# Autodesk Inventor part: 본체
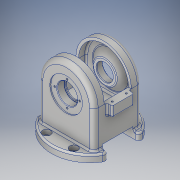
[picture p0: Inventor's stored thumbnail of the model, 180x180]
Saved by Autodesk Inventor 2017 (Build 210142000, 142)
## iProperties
Part Number: 본체
Material: 알루미늄 6061
Document SubType Name: Modeling
Designer: MRC
Density: 2.7 g/cm^3
Appearance: 알루미늄 - 평지
Mass: 1198.45 g
Surface Area: 1058.11 cm^2
Volume: 443.871 cm^3
Author: MRC
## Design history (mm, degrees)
sketch "스케치1"
  geometry: C1 r 71 at (0, 0); 1 further point
  constraints: 1 centre point, 1 coincident
  dimensions: "d0" = 142 diameter of C1
extrude "돌출1" new body sketch "스케치1" distance "d1" = 13; taper "d2" = 0 deg
sketch "스케치2"
  geometry: L1 (-71, 0)-(71, 0) reference; L2 (-51, 81)-(-51, 0); L3 (51, 81)-(51, 0); L4 (-51, 0)-(51, 0); A1 r 51 centre (0, 81) between (-51, 81) and (51, 81); 1 further point
  constraints: 6 end point, 2 point on circle, 2 point on line, 2 tangent, 1 centre point, 1 horizontal, 1 parallel, 1 perpendicular, 1 vertical alignment
  dimensions: "d3" = 102 diameter of A1; "d4" = 81 distance from line of A1.centre L1
extrude "돌출2" join sketch "스케치2" stored distance "d5" = 88; taper "d6" = 0 deg
node "작업 평면1"
sketch "스케치4"
  geometry: L1 (61, -20)-(-61, -20); L2 (-61, -20)-(-61, 20); L3 (-61, 20)-(61, 20); L4 (61, 20)-(61, -20); L5 (61, -20)-(-61, 20); L6 (-61, -20)-(61, 20); 1 further point
  constraints: 12 end point, 2 midpoint, 2 parallel, 1 horizontal, 1 perpendicular
  dimensions: "d10" = 40 distance of L3.end L1.start; "d11" = 122 distance of L1.start L1.end
extrude "돌출3" join sketch "스케치4" distance "d12" = 20; taper "d13" = 0 deg
sketch "스케치5"
  geometry: L1 (-89.487, -28)-(89.487, -28); L2 (89.487, -28)-(89.487, 28); L3 (89.487, 28)-(-89.487, 28); L4 (-89.487, 28)-(-89.487, -28); L5 (-89.487, -28)-(89.487, 28); L6 (89.487, -28)-(-89.487, 28); 1 further point
  constraints: 12 end point, 2 midpoint, 2 parallel, 1 horizontal, 1 perpendicular
  dimensions: "d14" = 56 distance of L1.end L2.end; "d15" = 178.97487 distance of L2.end L3.end
extrude "돌출4" cut sketch "스케치5" distance "d16" = 19; taper "d17" = 0 deg
sketch "스케치6"
  geometry: L1 (-51, 13)-(51, 13) reference; L2 (-51, 13)-(-51, 81) reference; L3 (51, 81)-(51, 13) reference; L4 (-46, 81)-(-46, 40); L5 (46, 40)-(46, 81); L6 (65.246, 0)-(-65.246, 0) reference; L7 (-46, 40)-(46, 40); A1 r 51 centre (0, 81) between (51, 81) and (-51, 81) reference; A2 r 46 centre (0, 81) between (46, 81) and (-46, 81); 1 further point
  constraints: 6 end point, 2 point on circle, 1 centre point, 1 horizontal
  dimensions: "d18" = 5 radial gap between concentric circles of A1 A2; "d20" = 5 distance between parallel lines of L3 L5; "d21" = 5 distance between parallel lines of L2 L4; "d22" = 40 distance between parallel lines of L6 L7
extrude "돌출5" cut sketch "스케치6" stored distance "d23" = 78; taper "d24" = 0 deg
sketch "스케치7"
  geometry: L1 (201.818, -25)-(81, -25); L2 (81, -25)-(81, 25); L3 (81, 25)-(201.818, 25); L4 (201.818, 25)-(201.818, -25); L5 (0, 71)-(0, 28) reference; 2 further points
  constraints: 8 end point, 2 parallel, 1 horizontal, 1 horizontal alignment, 1 midpoint, 1 perpendicular
  dimensions: "d25" = 50 distance of L3.end L1.start; "d26" = 81 distance between parallel lines of L2 L5; "d27" = 120.81817 distance of L2.end L3.end
extrude "돌출6" cut sketch "스케치7" stored distance "d28" = 78; taper "d29" = 0 deg
sketch "스케치8"
  geometry: L1 (81, -25)-(81, 25) reference; L2 (81, -44)-(81, -25) reference; L3 (13, 44)-(81, 44) reference; L4 (81, -44)-(13, -44) reference; L5 (81, -44)-(132, -44) reference; L6 (132, 44)-(81, 44) reference; L7 (81, 25)-(81, 39) reference; L8 (81, -44)-(81, 44); L9 (102.5, -27)-(81, -27); L10 (81, -39)-(127, -39) reference; L11 (102.5, -27)-(114.5, -39); L12 (81, -39)-(114.5, -39); L13 (127, -39)-(127, -25) reference; L14 (81, -39)-(40, -39) reference; L15 (81, -39)-(81, -27); 1 further point
  constraints: 10 end point, 2 point on line, 1 collinear, 1 horizontal, 1 perpendicular, 1 vertical
  dimensions: "d30" = 12 horizontal distance of L9.start L11.end; "d31" = 45 deg angle of L11 L13; "d32" = 67 diameter of L11.end L2
revolve "회전1" sketch "스케치8" stored, may be unused: angle "d33" = 90 deg
sketch "스케치9"
  geometry: L1 (-65.246, 0)-(65.246, 0) reference; C1 r 30 at (0, 81); 2 further points
  constraints: 1 centre point, 1 midpoint, 1 vertical alignment
  dimensions: "d34" = 60 diameter of C1; "d35" = 81 distance from line of C1.centre L1
extrude "돌출7" cut sketch "스케치9" distance "d36" = 2; taper "d37" = 0 deg
sketch "스케치10"
  geometry: C1 r 30 at (0, 0) reference; C2 r 21.5 at (0, 0) reference; C3 r 18.5 at (0, 0); 1 further point
  constraints: 1 centre point, 1 coincident
  dimensions: "d38" = 37 diameter of C3
extrude "돌출8" cut sketch "스케치10" distance "d39" = 13; taper "d40" = 0 deg
sketch "스케치11"
  geometry: C1 r 30 at (0, 0) reference; C2 r 16 at (0, 0); 1 further point
  constraints: 1 centre point, 1 coincident
  dimensions: "d41" = 32 diameter of C2
extrude "돌출9" cut sketch "스케치11" distance "d42" = 13; taper "d43" = 0 deg
sketch "스케치12"
  geometry: C1 r 16 at (0, 0) reference; A1 r 23 centre (0, 0) between (23, 0) and (0, 23); 3 further points
  constraints: 4 point on circle, 2 horizontal alignment, 2 vertical alignment, 1 centre point, 1 coincident
  dimensions: "d44" = 46 diameter of A1
hole "구멍1" sketch "스케치12" at (23, 0), (0, 23), (-23, 0), (0, -23) diameter "d45" = 3.242; stored, may be unused: countersink angle "d49" = 90 deg, drill point angle "d51" = 118 deg; dims "d46" = 8, "d47" = 4, "d48" = 2, "d50" = 10
sketch "스케치13"
  geometry: L1 (54, 13)-(-54, 13); L2 (-54, 13)-(-54, -13); L3 (-54, -13)-(54, -13); L4 (54, -13)-(54, 13); L5 (54, 13)-(-54, -13); L6 (-54, 13)-(54, -13); 5 further points
  constraints: 12 end point, 4 coincident, 2 midpoint, 2 parallel, 1 horizontal, 1 perpendicular
  dimensions: "d52" = 26 distance of L3.end L1.start; "d53" = 108 distance of L2.end L3.end
hole "구멍2" sketch "스케치13" at (54, 13), (54, -13), (-54, -13), (-54, 13) diameter "d54" = 3.242; stored, may be unused: countersink angle "d58" = 90 deg, drill point angle "d60" = 118 deg; dims "d55" = 8, "d56" = 4, "d57" = 2, "d59" = 10
sketch "스케치15"
  geometry: C1 r 30 at (0, 0); 1 further point
  constraints: 1 centre point, 1 coincident
  dimensions: "d69" = 60 diameter of C1
extrude "돌출10" cut sketch "스케치15" distance "d70" = 22; taper "d71" = 0 deg
sketch "스케치16"
  geometry: C1 r 14 at (0, 0); 1 further point
  constraints: 1 centre point, 1 coincident
  dimensions: "d72" = 28 diameter of C1
extrude "돌출11" cut sketch "스케치16" distance "d73" = 15; taper "d74" = 0 deg
sketch "스케치17"
  geometry: C1 r 11 at (0, 0); 1 further point
  constraints: 1 centre point, 1 coincident
  dimensions: "d75" = 22 diameter of C1
extrude "돌출12" cut sketch "스케치17" stored distance "d76" = 15; taper "d77" = 0 deg
sketch "스케치18"
  geometry: A1 r 23 centre (0, 0) between (23, 0) and (0, 23); 3 further points
  constraints: 4 point on circle, 2 horizontal alignment, 2 vertical alignment, 1 centre point, 1 coincident
  dimensions: "d78" = 46 diameter of A1
hole "구멍4" sketch "스케치18" at (23, 0), (0, 23), (-23, 0), (0, -23) diameter "d79" = 3.242; stored, may be unused: countersink angle "d83" = 90 deg, drill point angle "d85" = 118 deg; dims "d80" = 8, "d81" = 4, "d82" = 2, "d84" = 10
sketch "스케치19"
  geometry: L1 (25, 55)-(-25, 55); L2 (-25, 55)-(-25, -55); L3 (-25, -55)-(25, -55); L4 (25, -55)-(25, 55); L5 (25, 55)-(-25, -55); L6 (-25, 55)-(25, -55); 5 further points
  constraints: 12 end point, 4 coincident, 2 midpoint, 2 parallel, 1 horizontal, 1 perpendicular
  dimensions: "d86" = 110 distance of L3.end L1.start; "d87" = 50 distance of L2.end L3.end
hole "구멍5" sketch "스케치19" at (25, 55), (-25, 55), (-25, -55), (25, -55) diameter "d88" = 9; stored, may be unused: countersink angle "d92" = 90 deg, drill point angle "d94" = 118 deg; dims "d89" = 8, "d90" = 15, "d91" = 8.8, "d93" = 10
sketch "스케치20"
  geometry: L1 (-65.246, 0)-(65.246, 0) reference; 3 further points
  constraints: 1 midpoint, 1 vertical alignment, 1 other
  dimensions: "d95" = 30 distance from line of point (0, 30) L1
feature "엠보싱1" sketch "스케치20" dims "d96" = 0.5, "d97" = 0
fillet "모깎기1" dims "d98" = 8
fillet "모깎기2" dims "d99" = 6
fillet "모깎기3" dims "d100" = 3
fillet "모깎기4" dims "d101" = 3
fillet "모깎기5" dims "d102" = 3
fillet "모깎기6" dims "d103" = 3
fillet "모깎기7" dims "d104" = 3
chamfer "모따기1" distance "d105" = 1; stored, may be unused: second distance "d106" = 2, angle "d107" = 45 deg
fillet "모깎기8" dims "d108" = 0.3
node "솔리드1"
mirror "미러1"
mirror "미러2"
mirror "미러3"
node "투영된 루프1"
other parameters: "d9" = 81
